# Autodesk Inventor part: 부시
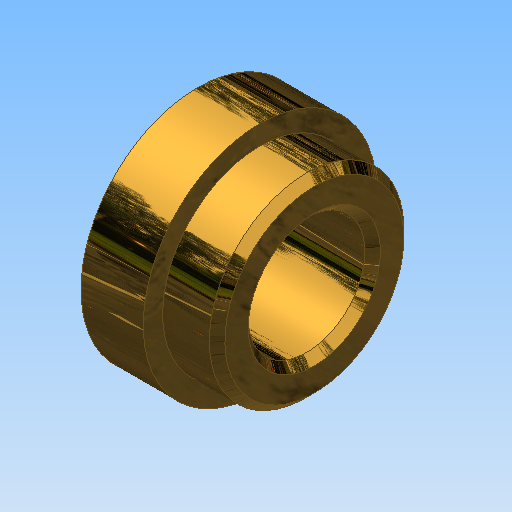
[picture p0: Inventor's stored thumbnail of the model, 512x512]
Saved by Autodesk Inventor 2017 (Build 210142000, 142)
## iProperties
Created: 2016-05
Part Number: 부시
Document SubType Name: Modeling
Designer: mduedu
Density: 7.86 g/cm^3
Material: 강철, 연강
Appearance: 황동 - 새틴
Author: mduedu
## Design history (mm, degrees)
sketch "스케치1"
  geometry: L1 (0, 0)-(15, 0); L2 (0, 7.5)-(15, 7.5); L3 (15, 7.5)-(15, 12.5); L4 (15, 12.5)-(8, 12.5); L5 (8, 12.5)-(8, 15); L6 (8, 15)-(0, 15); L7 (0, 15)-(0, 7.5)
  constraints: 14 end point, 4 parallel, 2 vertical alignment, 1 horizontal, 1 perpendicular, 1 vertical
  dimensions: "d0" = 15 distance of L1.start L1.end; "d1" = 15 diameter of L2 L1; "d2" = 25 diameter of L4 L1; "d3" = 8 distance of L5.end L6.end; "d4" = 30 diameter of L6 L1
revolve "회전1" sketch "스케치1" stored, may be unused: angle "d5" = 90 deg
chamfer "모따기1" distance "d6" = 1; stored, may be unused: second distance "d7" = 2, angle "d8" = 45 deg
chamfer "모따기2" distance "d9" = 1; stored, may be unused: second distance "d10" = 2, angle "d11" = 45 deg
node "솔리드1"
